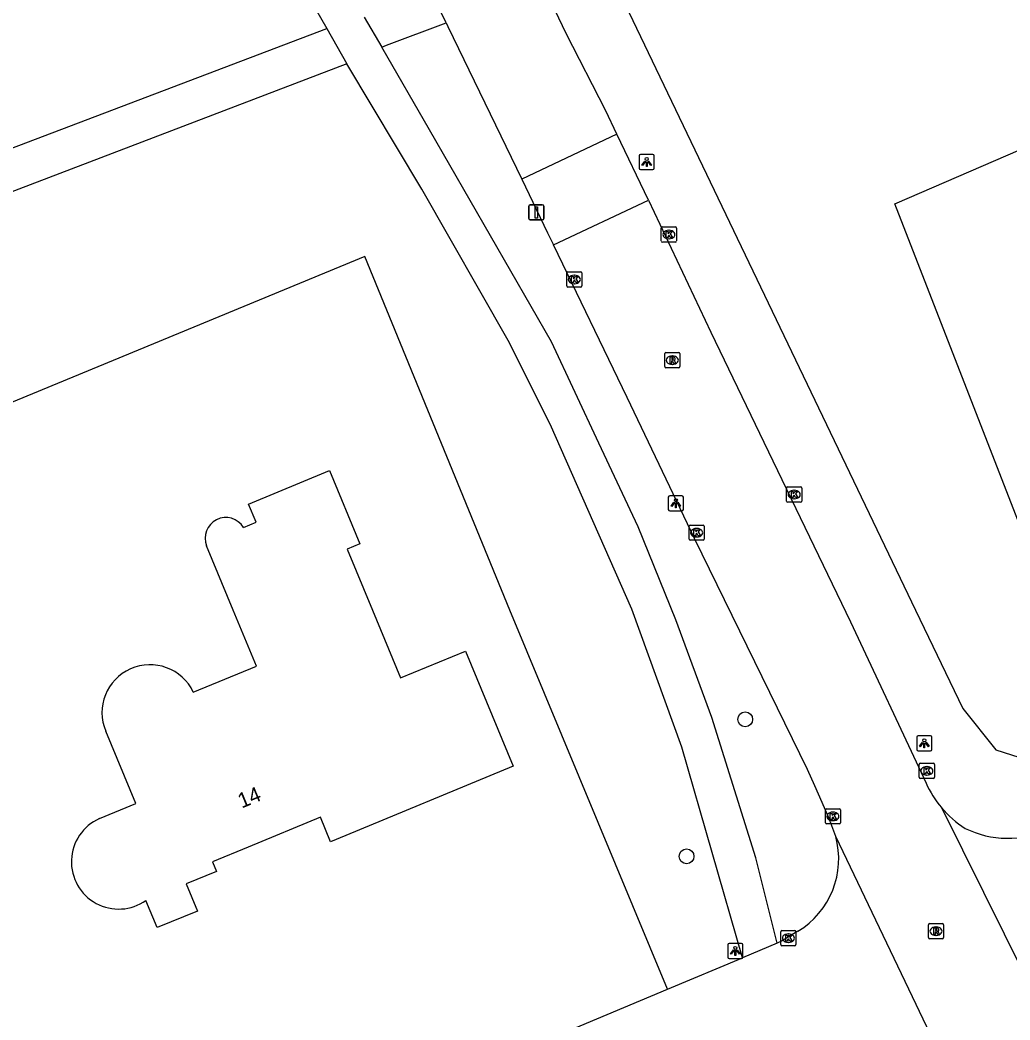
# Model space of a CAD drawing. Extents: x 162417 to 163721, y 384268 to 385416.
# Drawn here: x 163286.2 to 163351.6, y 384972.9 to 385039 of the extents above; entities that cross this region are included whole.
import ezdxf

# ---------------------------------------------------------------- set-up
doc = ezdxf.new("R2010")
doc.units = 0
for name, color, linetype in [('IMGEO_Afsluitpaal', 7, 'Continuous'), ('IMGEO_Berm_groen', 7, 'Continuous'), ('IMGEO_Boom', 7, 'Continuous'), ('IMGEO_Gemengd_bos', 7, 'Continuous'), ('IMGEO_Kolk', 7, 'Continuous'), ('IMGEO_Lichtpunt', 7, 'Continuous'), ('IMGEO_Loofbos', 7, 'Continuous'), ('IMGEO_Pand', 7, 'Continuous'), ('IMGEO_Pand_nummerreeks', 7, 'Continuous'), ('IMGEO_Rijbaan_lokaal_gesloten', 7, 'Continuous'), ('IMGEO_Rijbaan_lokaal_open', 7, 'Continuous'), ('IMGEO_Rioolput', 7, 'Continuous'), ('IMGEO_Voetpad_halfverhard', 7, 'Continuous'), ('IMGEO_Voetpad_open', 7, 'Continuous')]:
    doc.layers.add(name, color=color, linetype=linetype)

msp = doc.modelspace()

# ---------------------------------------------------------------- linework, layer by layer
at = {"layer": 'IMGEO_Afsluitpaal'}
for p, q in [((163319.9, 385026.769), (163320.69, 385026.769)), ((163320.69, 385026.769), (163319.9, 385026.769)), ((163319.8, 385025.869), (163319.8, 385026.669)), ((163319.8, 385026.669), (163319.8, 385025.869)), ((163320.79, 385026.669), (163320.79, 385025.869)), ((163320.79, 385025.869), (163320.79, 385026.669)), ((163320.69, 385025.769), (163319.9, 385025.769)), ((163319.9, 385025.769), (163320.69, 385025.769))]:
    msp.add_line(p, q, dxfattribs=at)
msp.add_lwpolyline([(163320.22, 385026.644), (163320.37, 385026.644), (163320.37, 385025.894), (163320.22, 385025.894), (163320.22, 385026.644)], dxfattribs=at)
for centre, start, end in [((163319.9, 385026.669), 90, 180), ((163319.9, 385026.669), 90, 180), ((163320.69, 385026.669), 0, 90), ((163320.69, 385026.669), 360, 90), ((163319.9, 385025.869), 180, 270), ((163319.9, 385025.869), 180, 270), ((163320.69, 385025.869), 270, 0), ((163320.69, 385025.869), 270, 0)]:
    msp.add_arc(centre, 0.1, start, end, dxfattribs=at)
at = {"layer": 'IMGEO_Berm_groen'}
msp.add_lwpolyline([(163325.132, 385042.177), (163345.34, 385000), (163348.459, 384993.49), (163350.645, 384990.763), (163353.753, 384989.786), (163357.745, 384991.405)], dxfattribs=at)
at = {"layer": 'IMGEO_Boom'}
for centre in [(163334.09, 384992.781), (163330.218, 384983.731)]:
    msp.add_circle(centre, 0.489, dxfattribs=at)
at = {"layer": 'IMGEO_Gemengd_bos'}
msp.add_lwpolyline([(163328.962, 384974.963), (163318.553, 385000), (163308.966, 385023.36), (163277.359, 385010.294)], dxfattribs=at)
at = {"layer": 'IMGEO_Kolk'}
for p, q in [((163328.551, 385024.378), (163328.551, 385025.23)), ((163328.626, 385025.304), (163329.478, 385025.304)), ((163329.039, 385025.084), (163329.064, 385025.084)), ((163329.552, 385025.23), (163329.552, 385024.378)), ((163329.478, 385024.304), (163328.626, 385024.304)), ((163329.062, 385024.524), (163329.037, 385024.524)), ((163322.307, 385021.413), (163322.307, 385022.265)), ((163322.382, 385022.339), (163323.234, 385022.339)), ((163323.308, 385022.265), (163323.308, 385021.413)), ((163322.818, 385021.559), (163322.793, 385021.559)), ((163322.795, 385022.119), (163322.82, 385022.119)), ((163323.234, 385021.339), (163322.382, 385021.339)), ((163336.824, 385007.205), (163336.824, 385008.057)), ((163336.899, 385008.131), (163337.751, 385008.131)), ((163337.312, 385007.911), (163337.337, 385007.911)), ((163337.825, 385008.057), (163337.825, 385007.205)), ((163337.751, 385007.131), (163336.899, 385007.131)), ((163337.335, 385007.351), (163337.31, 385007.351)), ((163330.385, 385004.683), (163330.385, 385005.535)), ((163330.46, 385005.609), (163331.312, 385005.609)), ((163330.873, 385005.389), (163330.898, 385005.389)), ((163331.386, 385005.535), (163331.386, 385004.683)), ((163331.312, 385004.609), (163330.46, 385004.609)), ((163330.896, 385004.829), (163330.871, 385004.829)), ((163345.583, 384988.955), (163345.583, 384989.807)), ((163345.658, 384989.881), (163346.51, 384989.881)), ((163346.584, 384989.807), (163346.584, 384988.955)), ((163346.071, 384989.661), (163346.096, 384989.661)), ((163346.51, 384988.881), (163345.658, 384988.881)), ((163346.094, 384989.101), (163346.069, 384989.101)), ((163339.382, 384985.947), (163339.382, 384986.799)), ((163339.457, 384986.873), (163340.309, 384986.873)), ((163339.87, 384986.653), (163339.895, 384986.653)), ((163340.383, 384986.799), (163340.383, 384985.947)), ((163340.309, 384985.873), (163339.457, 384985.873)), ((163339.893, 384986.093), (163339.868, 384986.093)), ((163336.443, 384977.906), (163336.443, 384978.758)), ((163336.518, 384978.832), (163337.37, 384978.832)), ((163336.931, 384978.612), (163336.956, 384978.612)), ((163337.444, 384978.758), (163337.444, 384977.906)), ((163336.954, 384978.052), (163336.929, 384978.052)), ((163337.37, 384977.832), (163336.518, 384977.832))]:
    msp.add_line(p, q, dxfattribs=at)
for points in [[(163328.551, 385024.378), (163328.551, 385025.23)], [(163328.626, 385025.304), (163329.478, 385025.304)], [(163328.872, 385025.004), (163328.995, 385025.004), (163328.995, 385024.853), (163329.125, 385025.004), (163329.289, 385025.004), (163329.143, 385024.853), (163329.296, 385024.604), (163329.144, 385024.604), (163329.059, 385024.768), (163328.995, 385024.701), (163328.995, 385024.604), (163328.872, 385024.604), (163328.872, 385025.004)], [(163329.552, 385025.23), (163329.552, 385024.378)], [(163329.478, 385024.304), (163328.626, 385024.304)], [(163322.307, 385021.413), (163322.307, 385022.265)], [(163322.382, 385022.339), (163323.234, 385022.339)], [(163323.308, 385022.265), (163323.308, 385021.413)], [(163322.628, 385022.039), (163322.751, 385022.039), (163322.751, 385021.888), (163322.881, 385022.039), (163323.045, 385022.039), (163322.899, 385021.888), (163323.052, 385021.639), (163322.9, 385021.639), (163322.815, 385021.803), (163322.751, 385021.736), (163322.751, 385021.639), (163322.628, 385021.639), (163322.628, 385022.039)], [(163323.234, 385021.339), (163322.382, 385021.339)], [(163336.824, 385007.205), (163336.824, 385008.057)], [(163336.899, 385008.131), (163337.751, 385008.131)], [(163337.145, 385007.831), (163337.268, 385007.831), (163337.268, 385007.68), (163337.398, 385007.831), (163337.562, 385007.831), (163337.416, 385007.68), (163337.569, 385007.431), (163337.417, 385007.431), (163337.332, 385007.595), (163337.268, 385007.528), (163337.268, 385007.431), (163337.145, 385007.431), (163337.145, 385007.831)], [(163337.825, 385008.057), (163337.825, 385007.205)], [(163337.751, 385007.131), (163336.899, 385007.131)], [(163330.385, 385004.683), (163330.385, 385005.535)], [(163330.46, 385005.609), (163331.312, 385005.609)], [(163330.706, 385005.309), (163330.829, 385005.309), (163330.829, 385005.158), (163330.959, 385005.309), (163331.123, 385005.309), (163330.977, 385005.158), (163331.13, 385004.909), (163330.978, 385004.909), (163330.893, 385005.073), (163330.829, 385005.006), (163330.829, 385004.909), (163330.706, 385004.909), (163330.706, 385005.309)], [(163331.386, 385005.535), (163331.386, 385004.683)], [(163331.312, 385004.609), (163330.46, 385004.609)], [(163345.583, 384988.955), (163345.583, 384989.807)], [(163345.658, 384989.881), (163346.51, 384989.881)], [(163346.584, 384989.807), (163346.584, 384988.955)], [(163345.904, 384989.581), (163346.027, 384989.581), (163346.027, 384989.43), (163346.157, 384989.581), (163346.321, 384989.581), (163346.175, 384989.43), (163346.328, 384989.181), (163346.176, 384989.181), (163346.091, 384989.345), (163346.027, 384989.278), (163346.027, 384989.181), (163345.904, 384989.181), (163345.904, 384989.581)], [(163346.51, 384988.881), (163345.658, 384988.881)], [(163339.382, 384985.947), (163339.382, 384986.799)], [(163339.457, 384986.873), (163340.309, 384986.873)], [(163339.703, 384986.573), (163339.826, 384986.573), (163339.826, 384986.422), (163339.956, 384986.573), (163340.12, 384986.573), (163339.974, 384986.422), (163340.127, 384986.173), (163339.975, 384986.173), (163339.89, 384986.337), (163339.826, 384986.27), (163339.826, 384986.173), (163339.703, 384986.173), (163339.703, 384986.573)], [(163340.383, 384986.799), (163340.383, 384985.947)], [(163340.309, 384985.873), (163339.457, 384985.873)], [(163336.443, 384977.906), (163336.443, 384978.758)], [(163336.518, 384978.832), (163337.37, 384978.832)], [(163337.444, 384978.758), (163337.444, 384977.906)], [(163336.764, 384978.532), (163336.887, 384978.532), (163336.887, 384978.381), (163337.017, 384978.532), (163337.181, 384978.532), (163337.035, 384978.381), (163337.188, 384978.132), (163337.036, 384978.132), (163336.951, 384978.296), (163336.887, 384978.229), (163336.887, 384978.132), (163336.764, 384978.132), (163336.764, 384978.532)], [(163337.37, 384977.832), (163336.518, 384977.832)]]:
    msp.add_lwpolyline(points, dxfattribs=at)
for centre, start, end in [((163328.628, 385025.228), 91.55205, 178.44795), ((163328.628, 385025.228), 91.55205, 178.44795), ((163329.476, 385025.228), 1.55205, 88.44795), ((163329.476, 385025.228), 1.55205, 88.44795), ((163328.628, 385024.38), 181.55205, 268.44795), ((163328.628, 385024.38), 181.55205, 268.44795), ((163329.476, 385024.38), 271.55205, 358.44795), ((163329.476, 385024.38), 271.55205, 358.44795), ((163322.384, 385022.263), 91.55205, 178.44795), ((163322.384, 385022.263), 91.55205, 178.44795), ((163323.232, 385022.263), 1.55205, 88.44795), ((163323.232, 385022.263), 1.55205, 88.44795), ((163322.384, 385021.415), 181.55205, 268.44795), ((163322.384, 385021.415), 181.55205, 268.44795), ((163323.232, 385021.415), 271.55205, 358.44795), ((163323.232, 385021.415), 271.55205, 358.44795), ((163336.901, 385008.055), 91.55205, 178.44795), ((163336.901, 385008.055), 91.55205, 178.44795), ((163337.749, 385008.055), 1.55205, 88.44795), ((163337.749, 385008.055), 1.55205, 88.44795), ((163336.901, 385007.207), 181.55205, 268.44795), ((163336.901, 385007.207), 181.55205, 268.44795), ((163337.749, 385007.207), 271.55205, 358.44795), ((163337.749, 385007.207), 271.55205, 358.44795), ((163330.462, 385005.533), 91.55205, 178.44795), ((163330.462, 385005.533), 91.55205, 178.44795), ((163331.31, 385005.533), 1.55205, 88.44795), ((163331.31, 385005.533), 1.55205, 88.44795), ((163330.462, 385004.685), 181.55205, 268.44795), ((163330.462, 385004.685), 181.55205, 268.44795), ((163331.31, 385004.685), 271.55205, 358.44795), ((163331.31, 385004.685), 271.55205, 358.44795), ((163345.66, 384989.805), 91.55205, 178.44795), ((163345.66, 384989.805), 91.55205, 178.44795), ((163346.508, 384989.805), 1.55205, 88.44795), ((163346.508, 384989.805), 1.55205, 88.44795), ((163345.66, 384988.957), 181.55205, 268.44795), ((163345.66, 384988.957), 181.55205, 268.44795), ((163346.508, 384988.957), 271.55205, 358.44795), ((163346.508, 384988.957), 271.55205, 358.44795), ((163339.459, 384986.797), 91.55205, 178.44795), ((163339.459, 384986.797), 91.55205, 178.44795), ((163340.307, 384986.797), 1.55205, 88.44795), ((163340.307, 384986.797), 1.55205, 88.44795), ((163339.459, 384985.949), 181.55205, 268.44795), ((163339.459, 384985.949), 181.55205, 268.44795), ((163340.307, 384985.949), 271.55205, 358.44795), ((163340.307, 384985.949), 271.55205, 358.44795), ((163336.52, 384978.756), 91.55205, 178.44795), ((163336.52, 384978.756), 91.55205, 178.44795), ((163337.368, 384978.756), 1.55205, 88.44795), ((163337.368, 384978.756), 1.55205, 88.44795), ((163336.52, 384977.908), 181.55205, 268.44795), ((163336.52, 384977.908), 181.55205, 268.44795), ((163337.368, 384977.908), 271.55205, 358.44795), ((163337.368, 384977.908), 271.55205, 358.44795)]:
    msp.add_arc(centre, 0.0765, start, end, dxfattribs=at)
for centre, major_axis, ratio, start_param, end_param in [((163329.038, 385024.804), (-0.387, 0.002), 0.722429, 4.712389, 7.853982), ((163329.063, 385024.804), (-0.39, 0.002), 0.717154, 1.570796, 4.712389), ((163322.794, 385021.839), (-0.387, 0.002), 0.722429, 4.712389, 7.853982), ((163322.819, 385021.839), (-0.39, 0.002), 0.717154, 1.570796, 4.712389), ((163337.311, 385007.631), (-0.387, 0.002), 0.722429, 4.712389, 7.853982), ((163337.336, 385007.631), (-0.39, 0.002), 0.717154, 1.570796, 4.712389), ((163330.872, 385005.109), (-0.387, 0.002), 0.722429, 4.712389, 7.853982), ((163330.897, 385005.109), (-0.39, 0.002), 0.717154, 1.570796, 4.712389), ((163346.07, 384989.381), (-0.387, 0.002), 0.722429, 4.712389, 7.853982), ((163346.095, 384989.381), (-0.39, 0.002), 0.717154, 1.570796, 4.712389), ((163339.869, 384986.373), (-0.387, 0.002), 0.722429, 4.712389, 7.853982), ((163339.894, 384986.373), (-0.39, 0.002), 0.717154, 1.570796, 4.712389), ((163336.93, 384978.332), (-0.387, 0.002), 0.722429, 4.712389, 7.853982), ((163336.955, 384978.332), (-0.39, 0.002), 0.717154, 1.570796, 4.712389)]:
    msp.add_ellipse(centre, major_axis=major_axis, ratio=ratio, start_param=start_param, end_param=end_param, dxfattribs=at)
at = {"layer": 'IMGEO_Lichtpunt'}
for p, q in [((163327.99, 385030.091), (163327.182, 385030.091)), ((163327.99, 385030.091), (163327.182, 385030.091)), ((163327.088, 385029.996), (163327.088, 385029.189)), ((163327.088, 385029.996), (163327.088, 385029.189)), ((163328.084, 385029.189), (163328.084, 385029.996)), ((163328.084, 385029.189), (163328.084, 385029.996)), ((163327.182, 385029.095), (163327.99, 385029.095)), ((163327.182, 385029.095), (163327.99, 385029.095)), ((163329.014, 385007.459), (163329.014, 385006.652)), ((163329.014, 385007.459), (163329.014, 385006.652)), ((163329.916, 385007.554), (163329.108, 385007.554)), ((163329.916, 385007.554), (163329.108, 385007.554)), ((163330.01, 385006.652), (163330.01, 385007.459)), ((163330.01, 385006.652), (163330.01, 385007.459)), ((163329.108, 385006.558), (163329.916, 385006.558)), ((163329.108, 385006.558), (163329.916, 385006.558)), ((163345.416, 384991.603), (163345.416, 384990.796)), ((163345.416, 384991.603), (163345.416, 384990.796)), ((163346.318, 384991.698), (163345.51, 384991.698)), ((163346.318, 384991.698), (163345.51, 384991.698)), ((163346.412, 384990.796), (163346.412, 384991.603)), ((163346.412, 384990.796), (163346.412, 384991.603)), ((163345.51, 384990.702), (163346.318, 384990.702)), ((163345.51, 384990.702), (163346.318, 384990.702)), ((163332.939, 384977.892), (163332.939, 384977.085)), ((163332.939, 384977.892), (163332.939, 384977.085)), ((163333.841, 384977.987), (163333.033, 384977.987)), ((163333.841, 384977.987), (163333.033, 384977.987)), ((163333.935, 384977.085), (163333.935, 384977.892)), ((163333.935, 384977.085), (163333.935, 384977.892)), ((163333.033, 384976.991), (163333.841, 384976.991)), ((163333.033, 384976.991), (163333.841, 384976.991))]:
    msp.add_line(p, q, dxfattribs=at)
for points in [[(163327.462, 385029.66), (163327.501, 385029.632), (163327.313, 385029.37), (163327.275, 385029.397), (163327.462, 385029.66)], [(163327.564, 385029.612), (163327.611, 385029.612), (163327.611, 385029.29), (163327.564, 385029.29), (163327.564, 385029.612)], [(163327.674, 385029.632), (163327.712, 385029.659), (163327.899, 385029.397), (163327.86, 385029.369), (163327.674, 385029.632)], [(163329.388, 385007.123), (163329.427, 385007.095), (163329.239, 385006.833), (163329.201, 385006.86), (163329.388, 385007.123)], [(163329.49, 385007.075), (163329.537, 385007.075), (163329.537, 385006.753), (163329.49, 385006.753), (163329.49, 385007.075)], [(163329.6, 385007.095), (163329.638, 385007.122), (163329.825, 385006.86), (163329.786, 385006.832), (163329.6, 385007.095)], [(163345.79, 384991.267), (163345.829, 384991.239), (163345.641, 384990.977), (163345.603, 384991.004), (163345.79, 384991.267)], [(163345.892, 384991.219), (163345.939, 384991.219), (163345.939, 384990.897), (163345.892, 384990.897), (163345.892, 384991.219)], [(163346.002, 384991.239), (163346.04, 384991.266), (163346.227, 384991.004), (163346.188, 384990.976), (163346.002, 384991.239)], [(163333.313, 384977.556), (163333.352, 384977.528), (163333.164, 384977.266), (163333.126, 384977.293), (163333.313, 384977.556)], [(163333.415, 384977.508), (163333.462, 384977.508), (163333.462, 384977.186), (163333.415, 384977.186), (163333.415, 384977.508)], [(163333.525, 384977.528), (163333.563, 384977.555), (163333.75, 384977.293), (163333.711, 384977.265), (163333.525, 384977.528)]]:
    msp.add_lwpolyline(points, dxfattribs=at)
for centre in [(163327.587, 385029.794), (163329.513, 385007.257), (163345.915, 384991.401), (163333.438, 384977.69)]:
    msp.add_circle(centre, 0.0994, dxfattribs=at)
for centre, start, end in [((163327.182, 385029.996), 90, 180), ((163327.182, 385029.996), 90, 180), ((163327.99, 385029.996), 0, 90), ((163327.99, 385029.996), 0, 90), ((163327.182, 385029.189), 180, 270), ((163327.182, 385029.189), 180, 270), ((163327.99, 385029.189), 270, 0), ((163327.99, 385029.189), 270, 360), ((163329.108, 385007.459), 90, 180), ((163329.108, 385007.459), 90, 180), ((163329.916, 385007.459), 0, 90), ((163329.916, 385007.459), 0, 90), ((163329.108, 385006.652), 180, 270), ((163329.108, 385006.652), 180, 270), ((163329.916, 385006.652), 270, 0), ((163329.916, 385006.652), 270, 360), ((163345.51, 384991.603), 90, 180), ((163345.51, 384991.603), 90, 180), ((163346.318, 384991.603), 0, 90), ((163346.318, 384991.603), 0, 90), ((163345.51, 384990.796), 180, 270), ((163345.51, 384990.796), 180, 270), ((163346.318, 384990.796), 270, 0), ((163346.318, 384990.796), 270, 360), ((163333.033, 384977.892), 90, 180), ((163333.033, 384977.892), 90, 180), ((163333.841, 384977.892), 0, 90), ((163333.841, 384977.892), 0, 90), ((163333.033, 384977.085), 180, 270), ((163333.033, 384977.085), 180, 270), ((163333.841, 384977.085), 270, 0), ((163333.841, 384977.085), 270, 360)]:
    msp.add_arc(centre, 0.0946, start, end, dxfattribs=at)
at = {"layer": 'IMGEO_Loofbos'}
msp.add_lwpolyline([(163357.745, 384991.405), (163354.406, 385000), (163343.981, 385026.826), (163371.144, 385038.583), (163419.878, 385059.084), (163500, 385092.556), (163507.868, 385095.856), (163524.402, 385063.53), (163526.981, 385058.237)], dxfattribs=at)
at = {"layer": 'IMGEO_Pand'}
for points in [[(163300.965, 385005.456), (163301.797, 385005.801), (163301.299, 385007.006), (163306.649, 385009.218), (163308.65, 385004.379), (163307.805, 385004.029), (163309.472, 385000), (163311.324, 384995.519), (163315.613, 384997.293), (163318.761, 384989.681), (163307.088, 384984.854), (163306.714, 384984.699), (163306.046, 384986.314), (163301.276, 384984.342), (163298.92, 384983.368), (163299.179, 384982.742), (163297.177, 384981.915), (163297.918, 384980.123), (163295.267, 384979.026), (163294.523, 384980.826)], [(163297.647, 384994.577), (163301.819, 384996.302), (163300.29, 385000), (163298.517, 385004.24)], [(163291.445, 384986.227), (163293.846, 384987.235), (163291.863, 384992.002)]]:
    msp.add_lwpolyline(points, dxfattribs=at)
for centre, radius, start, end in [((163299.793, 385004.743), 1.372, 31.33987, 201.49025), ((163294.783, 384993.226), 3.166, 25.2476, 202.74905), ((163292.72, 384983.376), 3.123, 114.10288, 305.25427)]:
    msp.add_arc(centre, radius, start, end, dxfattribs=at)
at = {"layer": 'IMGEO_Rijbaan_lokaal_gesloten'}
for points in [[(163314.352, 385038.78), (163313.384, 385040.81)], [(163325.621, 385031.431), (163324.885, 385032.981), (163322.267, 385038.087), (163321.067, 385040.629)], [(163314.352, 385038.78), (163314.463, 385038.546), (163319.33, 385028.472)], [(163327.694, 385027.065), (163331.826, 385018.363), (163335.922, 385009.856), (163341.041, 384999.228), (163346.029, 384988.576)], [(163340.067, 384985.051), (163339.608, 384986.274), (163339.172, 384987.292), (163338.687, 384988.388), (163338.195, 384989.478), (163330.751, 385004.737), (163326.303, 385014.043), (163321.435, 385024.117)], [(163347.053, 384986.951), (163353.956, 384973.02)], [(163347.305, 384969.948), (163340.067, 384985.051)], [(163337.564, 384978.789), (163336.54, 384978.154), (163336.199, 384978.01)], [(163336.199, 384978.01), (163333.911, 384977.041)], [(163328.962, 384974.963), (163333.911, 384977.041)], [(163183.667, 384913.961), (163328.962, 384974.963)]]:
    msp.add_lwpolyline(points, dxfattribs=at)
for centre, radius, start, end in [((163352.323, 384991.407), 6.901, 204.21786, 220.21662), ((163352.326, 384991.396), 6.897, 220.13239, 237.41775), ((163351.397, 384991.135), 6.21, 243.35069, 295.62302), ((163334.7, 384983.565), 5.569, 300.94904, 15.47654)]:
    msp.add_arc(centre, radius, start, end, dxfattribs=at)
at = {"layer": 'IMGEO_Rijbaan_lokaal_open'}
for points in [[(163325.621, 385031.431), (163319.33, 385028.472)], [(163327.694, 385027.065), (163325.621, 385031.431)], [(163319.33, 385028.472), (163321.045, 385024.924), (163321.435, 385024.117)], [(163321.435, 385024.117), (163327.694, 385027.065)]]:
    msp.add_lwpolyline(points, dxfattribs=at)
at = {"layer": 'IMGEO_Rioolput'}
for p, q in [((163328.774, 385016.085), (163328.774, 385016.937)), ((163328.849, 385017.011), (163329.701, 385017.011)), ((163329.775, 385016.937), (163329.775, 385016.085)), ((163329.285, 385016.231), (163329.26, 385016.231)), ((163329.262, 385016.791), (163329.287, 385016.791)), ((163329.701, 385016.011), (163328.849, 385016.011)), ((163346.189, 384978.366), (163346.189, 384979.218)), ((163346.264, 384979.292), (163347.116, 384979.292)), ((163347.19, 384979.218), (163347.19, 384978.366)), ((163346.677, 384979.072), (163346.702, 384979.072)), ((163347.116, 384978.292), (163346.264, 384978.292)), ((163346.7, 384978.512), (163346.675, 384978.512))]:
    msp.add_line(p, q, dxfattribs=at)
for points in [[(163328.774, 385016.085), (163328.774, 385016.937)], [(163328.849, 385017.011), (163329.701, 385017.011)], [(163329.775, 385016.937), (163329.775, 385016.085)], [(163329.363, 385016.709), (163329.111, 385016.711), (163329.111, 385016.311)], [(163329.111, 385016.311), (163329.235, 385016.311), (163329.235, 385016.473), (163329.246, 385016.473)], [(163329.289, 385016.63), (163329.235, 385016.63), (163329.235, 385016.549)], [(163329.235, 385016.549), (163329.287, 385016.549)], [(163329.293, 385016.444), (163329.364, 385016.311), (163329.504, 385016.311), (163329.439, 385016.437)], [(163329.701, 385016.011), (163328.849, 385016.011)], [(163346.189, 384978.366), (163346.189, 384979.218)], [(163346.264, 384979.292), (163347.116, 384979.292)], [(163347.19, 384979.218), (163347.19, 384978.366)], [(163346.778, 384978.99), (163346.526, 384978.992), (163346.526, 384978.592)], [(163346.526, 384978.592), (163346.65, 384978.592), (163346.65, 384978.754), (163346.661, 384978.754)], [(163346.704, 384978.911), (163346.65, 384978.911), (163346.65, 384978.83)], [(163346.65, 384978.83), (163346.702, 384978.83)], [(163346.708, 384978.725), (163346.779, 384978.592), (163346.919, 384978.592), (163346.854, 384978.718)], [(163347.116, 384978.292), (163346.264, 384978.292)]]:
    msp.add_lwpolyline(points, dxfattribs=at)
for centre, radius, start, end in [((163328.851, 385016.935), 0.0765, 91.55205, 178.44795), ((163328.851, 385016.935), 0.0765, 91.55205, 178.44795), ((163329.699, 385016.935), 0.0765, 1.55205, 88.44795), ((163329.699, 385016.935), 0.0765, 1.55205, 88.44795), ((163329.245, 385016.42), 0.0533, 26.02933, 88.69889), ((163329.271, 385016.738), 0.19, 274.7715, 282.96867), ((163329.295, 385016.534), 0.0964, 77.00612, 93.18647), ((163329.309, 385016.591), 0.0378, 276.66336, 79.67722), ((163329.362, 385016.599), 0.109, 350.36119, 89.41601), ((163329.36, 385016.599), 0.112, 277.58423, 350.98172), ((163329.344, 385016.384), 0.108, 29.51342, 73.79051), ((163328.851, 385016.087), 0.0765, 181.55205, 268.44795), ((163328.851, 385016.087), 0.0765, 181.55205, 268.44795), ((163329.699, 385016.087), 0.0765, 271.55205, 358.44795), ((163329.699, 385016.087), 0.0765, 271.55205, 358.44795), ((163346.266, 384979.216), 0.0765, 91.55205, 178.44795), ((163346.266, 384979.216), 0.0765, 91.55205, 178.44795), ((163347.114, 384979.216), 0.0765, 1.55205, 88.44795), ((163347.114, 384979.216), 0.0765, 1.55205, 88.44795), ((163346.66, 384978.701), 0.0533, 26.02933, 88.69889), ((163346.686, 384979.019), 0.19, 274.7715, 282.96867), ((163346.71, 384978.815), 0.0964, 77.00612, 93.18647), ((163346.724, 384978.872), 0.0378, 276.66336, 79.67722), ((163346.777, 384978.88), 0.109, 350.36119, 89.41601), ((163346.775, 384978.88), 0.112, 277.58423, 350.98172), ((163346.759, 384978.665), 0.108, 29.51342, 73.79051), ((163346.266, 384978.368), 0.0765, 181.55205, 268.44795), ((163346.266, 384978.368), 0.0765, 181.55205, 268.44795), ((163347.114, 384978.368), 0.0765, 271.55205, 358.44795), ((163347.114, 384978.368), 0.0765, 271.55205, 358.44795)]:
    msp.add_arc(centre, radius, start, end, dxfattribs=at)
for centre, major_axis, ratio, start_param, end_param in [((163329.261, 385016.511), (-0.387, 0.002), 0.722429, 4.712389, 7.853982), ((163329.286, 385016.511), (-0.39, 0.002), 0.717154, 1.570796, 4.712389), ((163346.676, 384978.792), (-0.387, 0.002), 0.722429, 4.712389, 7.853982), ((163346.701, 384978.792), (-0.39, 0.002), 0.717154, 1.570796, 4.712389)]:
    msp.add_ellipse(centre, major_axis=major_axis, ratio=ratio, start_param=start_param, end_param=end_param, dxfattribs=at)
at = {"layer": 'IMGEO_Voetpad_halfverhard'}
for points in [[(163310.086, 385037.189), (163310.406, 385037.308), (163314.352, 385038.78)], [(163270.812, 385024.868), (163306.472, 385038.41)], [(163307.775, 385036.08), (163264.453, 385019.528)]]:
    msp.add_lwpolyline(points, dxfattribs=at)
at = {"layer": 'IMGEO_Voetpad_open'}
for points in [[(163291.632, 385064.162), (163306.472, 385038.41)], [(163308.94, 385039.17), (163310.086, 385037.189)], [(163306.472, 385038.41), (163307.775, 385036.08)], [(163336.199, 384978.01), (163334.793, 384983.636), (163331.877, 384992.906), (163329.506, 384999.362), (163327.026, 385005.491), (163324.433, 385011.035), (163321.305, 385017.726), (163313.243, 385031.731), (163310.086, 385037.189)], [(163333.911, 384977.041), (163329.908, 384990.952), (163326.615, 385000.058), (163321.211, 385012.274), (163318.448, 385017.802), (163312.737, 385027.803), (163307.775, 385036.08)]]:
    msp.add_lwpolyline(points, dxfattribs=at)

# ---------------------------------------------------------------- texts
at = {"layer": 'IMGEO_Pand_nummerreeks'}
msp.add_text('14', height=1, rotation=22.46097, dxfattribs=at).set_placement((163300.841, 384986.889))

doc.saveas('drawing.dxf')
